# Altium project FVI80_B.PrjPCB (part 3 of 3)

## Sheet FVI80_HV_Power_Connector.SchDoc
size 431 x 279 mm; Date: Not shown in title block; ApprovedBy: Not shown in title block; CheckedBy: Not shown in title block; Author: Not shown in title block; CompanyName: Not shown in title block; Engineer: Not shown in title block; Organization: Not shown in title block; Address1: Not shown in title block; Address2: Not shown in title block; Address3: Not shown in title block; Address4: Not shown in title block; DocumentNumber: 10; Revision: Use project parameter SCH_Rev; SheetNumber: 10; SheetTotal: 11; PageSetup: Record=PageOptions¦CenterHorizontal=True¦CenterVertical=True¦PrintScale=1.00¦XCorrection=1.00¦YCorrection=1.00¦PrintKind=0¦BorderSize=5000000¦LeftOffset=0¦BottomOffset=0¦Orientation=2¦PaperLength=1000¦PaperWidth=1000¦Scale=100¦PaperSource=15¦PrintQuality=600¦MediaType=1¦DitherType=10¦PaperKind=Letter¦PrintScaleMode=1
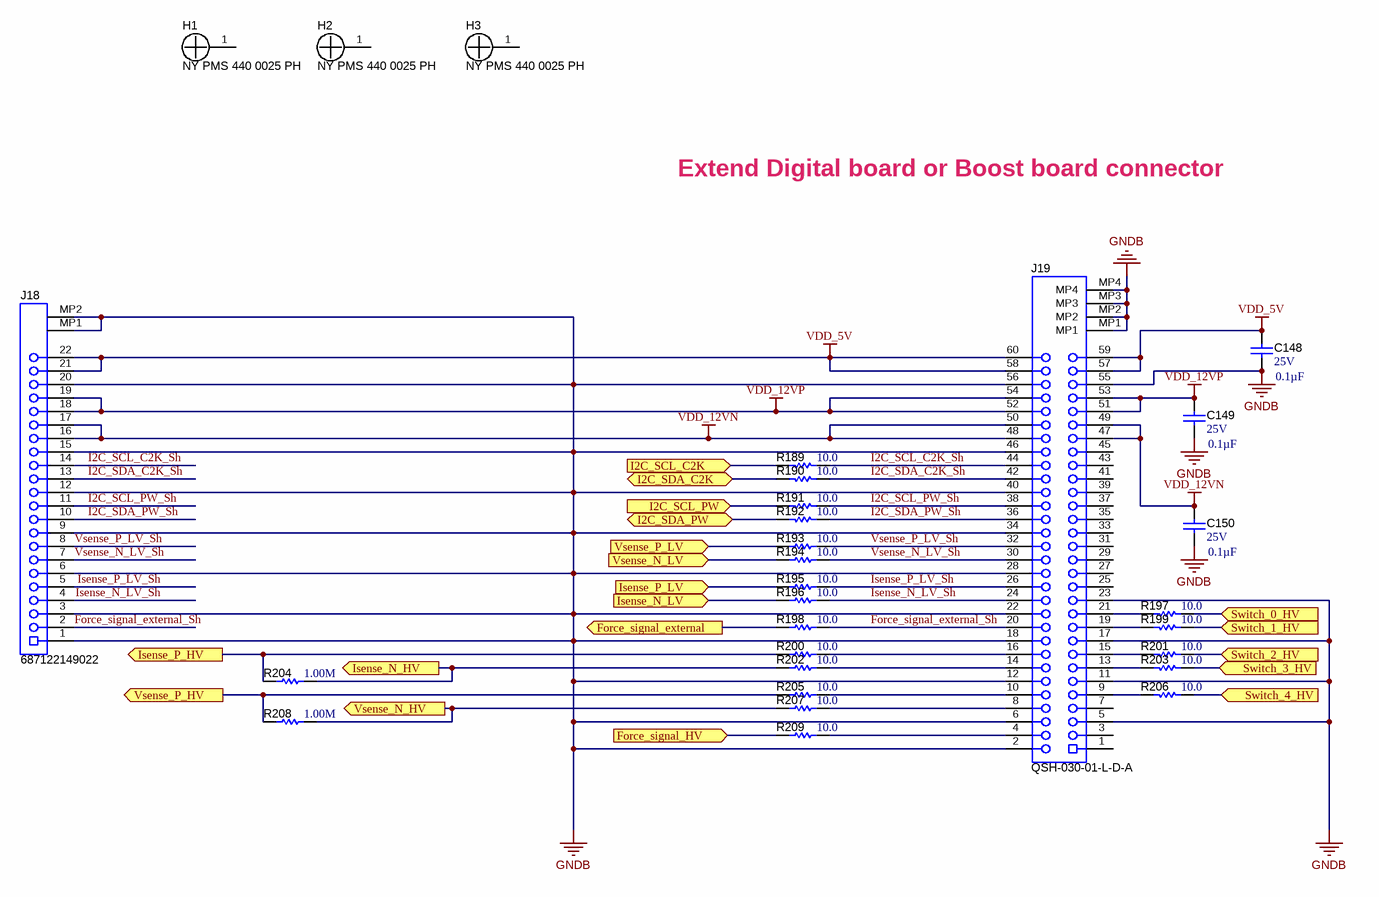
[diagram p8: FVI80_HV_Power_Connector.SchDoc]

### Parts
C148  VDC_V: 25V  ValueDisplayed: 0.1µF  [0402]  (hidden comment: CGA2B3X7R1E104K050BB)
C149  VDC_V: 25V  ValueDisplayed: 0.1µF  [0402]  (hidden comment: CGA2B3X7R1E104K050BB)
C150  VDC_V: 25V  ValueDisplayed: 0.1µF  [0402]  (hidden comment: CGA2B3X7R1E104K050BB)
H1  NY PMS 440 0025 PH  [NY PMS 440 0025 PH]
H2  NY PMS 440 0025 PH  [NY PMS 440 0025 PH]
H3  NY PMS 440 0025 PH  [NY PMS 440 0025 PH]
J18  687122149022  [Wurth_687122149022]
J19  QSH-030-01-L-D-A  [Samtec_QSH-030-01-X-D-A]
R189  ValueDisplayed: 10.0  [0402]  (hidden comment: MCR01MZPF10R0)
R190  ValueDisplayed: 10.0  [0402]  (hidden comment: MCR01MZPF10R0)
R191  ValueDisplayed: 10.0  [0402]  (hidden comment: MCR01MZPF10R0)
R192  ValueDisplayed: 10.0  [0402]  (hidden comment: MCR01MZPF10R0)
R193  ValueDisplayed: 10.0  [0402]  (hidden comment: CRCW040210R0FKED)
R194  ValueDisplayed: 10.0  [0402]  (hidden comment: CRCW040210R0FKED)
R195  ValueDisplayed: 10.0  [0402]  (hidden comment: CRCW040210R0FKED)
R196  ValueDisplayed: 10.0  [0402]  (hidden comment: CRCW040210R0FKED)
R197  ValueDisplayed: 10.0  [0402]  (hidden comment: MCR01MZPF10R0)
R198  ValueDisplayed: 10.0  [0402]  (hidden comment: CRCW040210R0FKED)
R199  ValueDisplayed: 10.0  [0402]  (hidden comment: MCR01MZPF10R0)
R200  ValueDisplayed: 10.0  [0402]  (hidden comment: CRCW040210R0FKED)
R201  ValueDisplayed: 10.0  [0402]  (hidden comment: MCR01MZPF10R0)
R202  ValueDisplayed: 10.0  [0402]  (hidden comment: CRCW040210R0FKED)
R203  ValueDisplayed: 10.0  [0402]  (hidden comment: MCR01MZPF10R0)
R204  ValueDisplayed: 1.00M  [0402]  (hidden comment: RC0402FR-071ML)
R205  ValueDisplayed: 10.0  [0402]  (hidden comment: CRCW040210R0FKED)
R206  ValueDisplayed: 10.0  [0402]  (hidden comment: MCR01MZPF10R0)
R207  ValueDisplayed: 10.0  [0402]  (hidden comment: CRCW040210R0FKED)
R208  ValueDisplayed: 1.00M  [0402]  (hidden comment: RC0402FR-071ML)
R209  ValueDisplayed: 10.0  [0402]  (hidden comment: CRCW040210R0FKED)

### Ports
Force_signal_external (out), Force_signal_HV (in), I2C_SCL_C2K (in), I2C_SCL_PW (in), I2C_SDA_C2K (bidir), I2C_SDA_PW (bidir), Isense_N_HV (out), Isense_N_LV (in), Isense_P_HV (out), Isense_P_LV (in), Switch_0_HV (in), Switch_1_HV (in), Switch_2_HV (in), Switch_3_HV (in), Switch_4_HV (in), Vsense_N_HV (out), Vsense_N_LV (in), Vsense_P_HV (out), Vsense_P_LV (in)

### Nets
GNDB: C148.2 C149.2 C150.2 J18.1 J18.3 J18.6 J18.9 J18.12 J18.15 J18.20 J18.MP1 J18.MP2 J19.2 J19.5 J19.6 J19.11 J19.12 J19.17 J19.18 J19.22 J19.23 J19.28 J19.34 J19.40 J19.46 J19.55 J19.56 J19.MP1 J19.MP2 J19.MP3 J19.MP4
VDD_5V: C148.1 J18.21 J18.22 J19.57 J19.58 J19.59 J19.60
VDD_12VN: C150.1 J18.16 J18.17 J19.47 J19.48 J19.49 J19.50
VDD_12VP: C149.1 J18.18 J18.19 J19.51 J19.52 J19.53 J19.54
Force_signal_external_Sh: J18.2 J19.20 R198.2
I2C_SCL_C2K_Sh: J18.14 J19.44 R189.2
I2C_SCL_IN: R189.1 ; port I2C_SCL_C2K
I2C_SCL_PW_Sh: J18.11 J19.38 R191.2
I2C_SDA_C2K_Sh: J18.13 J19.42 R190.2
I2C_SDA_IN: R190.1 ; port I2C_SDA_C2K
I2C_SDA_PW_Sh: J18.10 J19.36 R192.2
Isense_N_LV_Sh: J18.4 J19.24 R196.2
Isense_P_LV_Sh: J18.5 J19.26 R195.2
Vsense_N_LV_Sh: J18.7 J19.30 R194.2
Vsense_P_LV_Sh: J18.8 J19.32 R193.2
NetD1_2: R196.1 ; port Isense_N_LV
NetD2_2: R195.1 ; port Isense_P_LV
NetD3_2: R193.1 ; port Vsense_P_LV
NetD4_1: R194.1 ; port Vsense_N_LV
NetJ19_4: J19.4 R209.2
NetJ19_8: J19.8 R207.2
NetJ19_9: J19.9 R206.1
NetJ19_10: J19.10 R205.2
NetJ19_13: J19.13 R203.1
NetJ19_14: J19.14 R202.2
NetJ19_15: J19.15 R201.1
NetJ19_16: J19.16 R200.2
NetJ19_19: J19.19 R199.1
NetJ19_21: J19.21 R197.1
NetR114_1: R198.1 ; port Force_signal_external
NetR169_1: R192.1 ; port I2C_SDA_PW
NetR171_1: R191.1 ; port I2C_SCL_PW
NetR197_2: R197.2 ; port Switch_0_HV
NetR199_2: R199.2 ; port Switch_1_HV
NetR200_1: R200.1 R204.1 ; port Isense_P_HV
NetR201_2: R201.2 ; port Switch_2_HV
NetR202_1: R202.1 R204.2 ; port Isense_N_HV
NetR203_2: R203.2 ; port Switch_3_HV
NetR205_1: R205.1 R208.1 ; port Vsense_P_HV
NetR206_2: R206.2 ; port Switch_4_HV
NetR207_1: R207.1 R208.2 ; port Vsense_N_HV
NetR209_1: R209.1 ; port Force_signal_HV

Not connected (* = marked no-connect by the designer): H1 1; H2 1; H3 1; J19 1 3 7 25 27 29 31 33 35 37 39 41 43 45

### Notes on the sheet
- Extend Digital board or Boost board connector

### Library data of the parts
C148-C150 = CMP-0080610-1: CAP, CERM, 0.1 µF, 25 V,+/- 10%, X7R, AEC-Q200 Grade 1, 0402; Manufacturer: TDK; TaMin_C: -55°C; Polarized: N; SizeAreaWB_mm2: 3; U/M: EA; Value: 0.1uF; TaMax_C: 125°C; SizeZ_mm: 0.6; SizeX_mm: 1; SizeY_mm: 0.5; AEC Qualified: Y; Cap_F: 100nF; AEC Category: Q200
H1-H3 = CMP-0003617-1: Machine Screw, Round, #4-40 x 1/4, Nylon, Philips panhead; Manufacturer: B&F Fastener Supply; CompType: Hardware
J18 = CMP-0081902-1: FPC Connector, 0.5mm, 22 Pos, R/A, Tin, SMT; Manufacturer: Wurth Elektronik; Pitch_mm: 0.5; Gender: Female; Cert_UL: Y; Voltage_V: 50V; Current_A: 500mA; Row_Count: 1; CompType: FFC or FPC
J19 = CMP-0075524-1: Receptacle, 0.5 mm, 30x2, Gold, TH; Manufacturer: Samtec; Pitch_mm: 0.5; Gender: Female; Green_REACh: Passed; CT: False; Shrouded: N; RowSpacing_mm: 5.73; Green_Lifecycle: Active; Row_Count: 2
R189-R192 R197 R199 R201 R203 R206 = CMP-0025963-3: RES, 10.0, 1%, 0.063 W, AEC-Q200 Grade 0, 0402; Manufacturer: Vishay-Dale; PartNumber: CRCW040210R0FKED; Power_W: 63mW; TempCo: 100 ppm/C; Value_Code: 10R0; Value: 10.0; EIA_Code: E96; Res_ohm: 10; SizeX_mm: 1; SizeY_mm: 0.5; SizeZ_mm: 0.6; Value2: 0.063W; AEC Qualified: Y; VDC_V: 50V; AEC Category: Q200; AEC Grade: 0
R193-R196 R198 R200 R202 R205 R207 R209 = CMP-0025963-3: RES, 10.0, 1%, 0.063 W, AEC-Q200 Grade 0, 0402; Manufacturer: Vishay-Dale; Power_W: 63mW; TempCo: 100 ppm/C; Value_Code: 10R0; Value: 10.0; EIA_Code: E96; Res_ohm: 10; SizeX_mm: 1; SizeY_mm: 0.5; SizeZ_mm: 0.6; Value2: 0.063W; AEC Qualified: Y; VDC_V: 50V; AEC Category: Q200; AEC Grade: 0
R204 R208 = CMP-0026727-1: RES, 1.00 M, 1%, 0.063 W, 0402; Manufacturer: Yageo America; Power_W: 63mW; TempCo: 100 ppm/C; Value_Code: 1M00; U/M: EA; Value: 1.00Meg; EIA_Code: E96; Res_ohm: 1M; SizeX_mm: 1; SizeY_mm: 0.5; SizeZ_mm: 0.6; Value2: 0.063W; AEC Category: Q200

## Sheet FVI80_Signal_ADC93.SchDoc
size 431 x 279 mm; Date: Not shown in title block; ApprovedBy: Not shown in title block; CheckedBy: Not shown in title block; Author: Not shown in title block; CompanyName: Not shown in title block; Engineer: Not shown in title block; Organization: Not shown in title block; Address1: Not shown in title block; Address2: Not shown in title block; Address3: Not shown in title block; Address4: Not shown in title block; DocumentNumber: 7; Revision: Use project parameter SCH_Rev; SheetNumber: 7; SheetTotal: 11; PageSetup: Record=PageOptions¦CenterHorizontal=True¦CenterVertical=True¦PrintScale=1.00¦XCorrection=1.00¦YCorrection=1.00¦PrintKind=0¦BorderSize=5000000¦LeftOffset=0¦BottomOffset=0¦Orientation=2¦PaperLength=1000¦PaperWidth=1000¦Scale=100¦PaperSource=15¦PrintQuality=600¦MediaType=1¦DitherType=10¦PaperKind=Letter¦PrintScaleMode=1
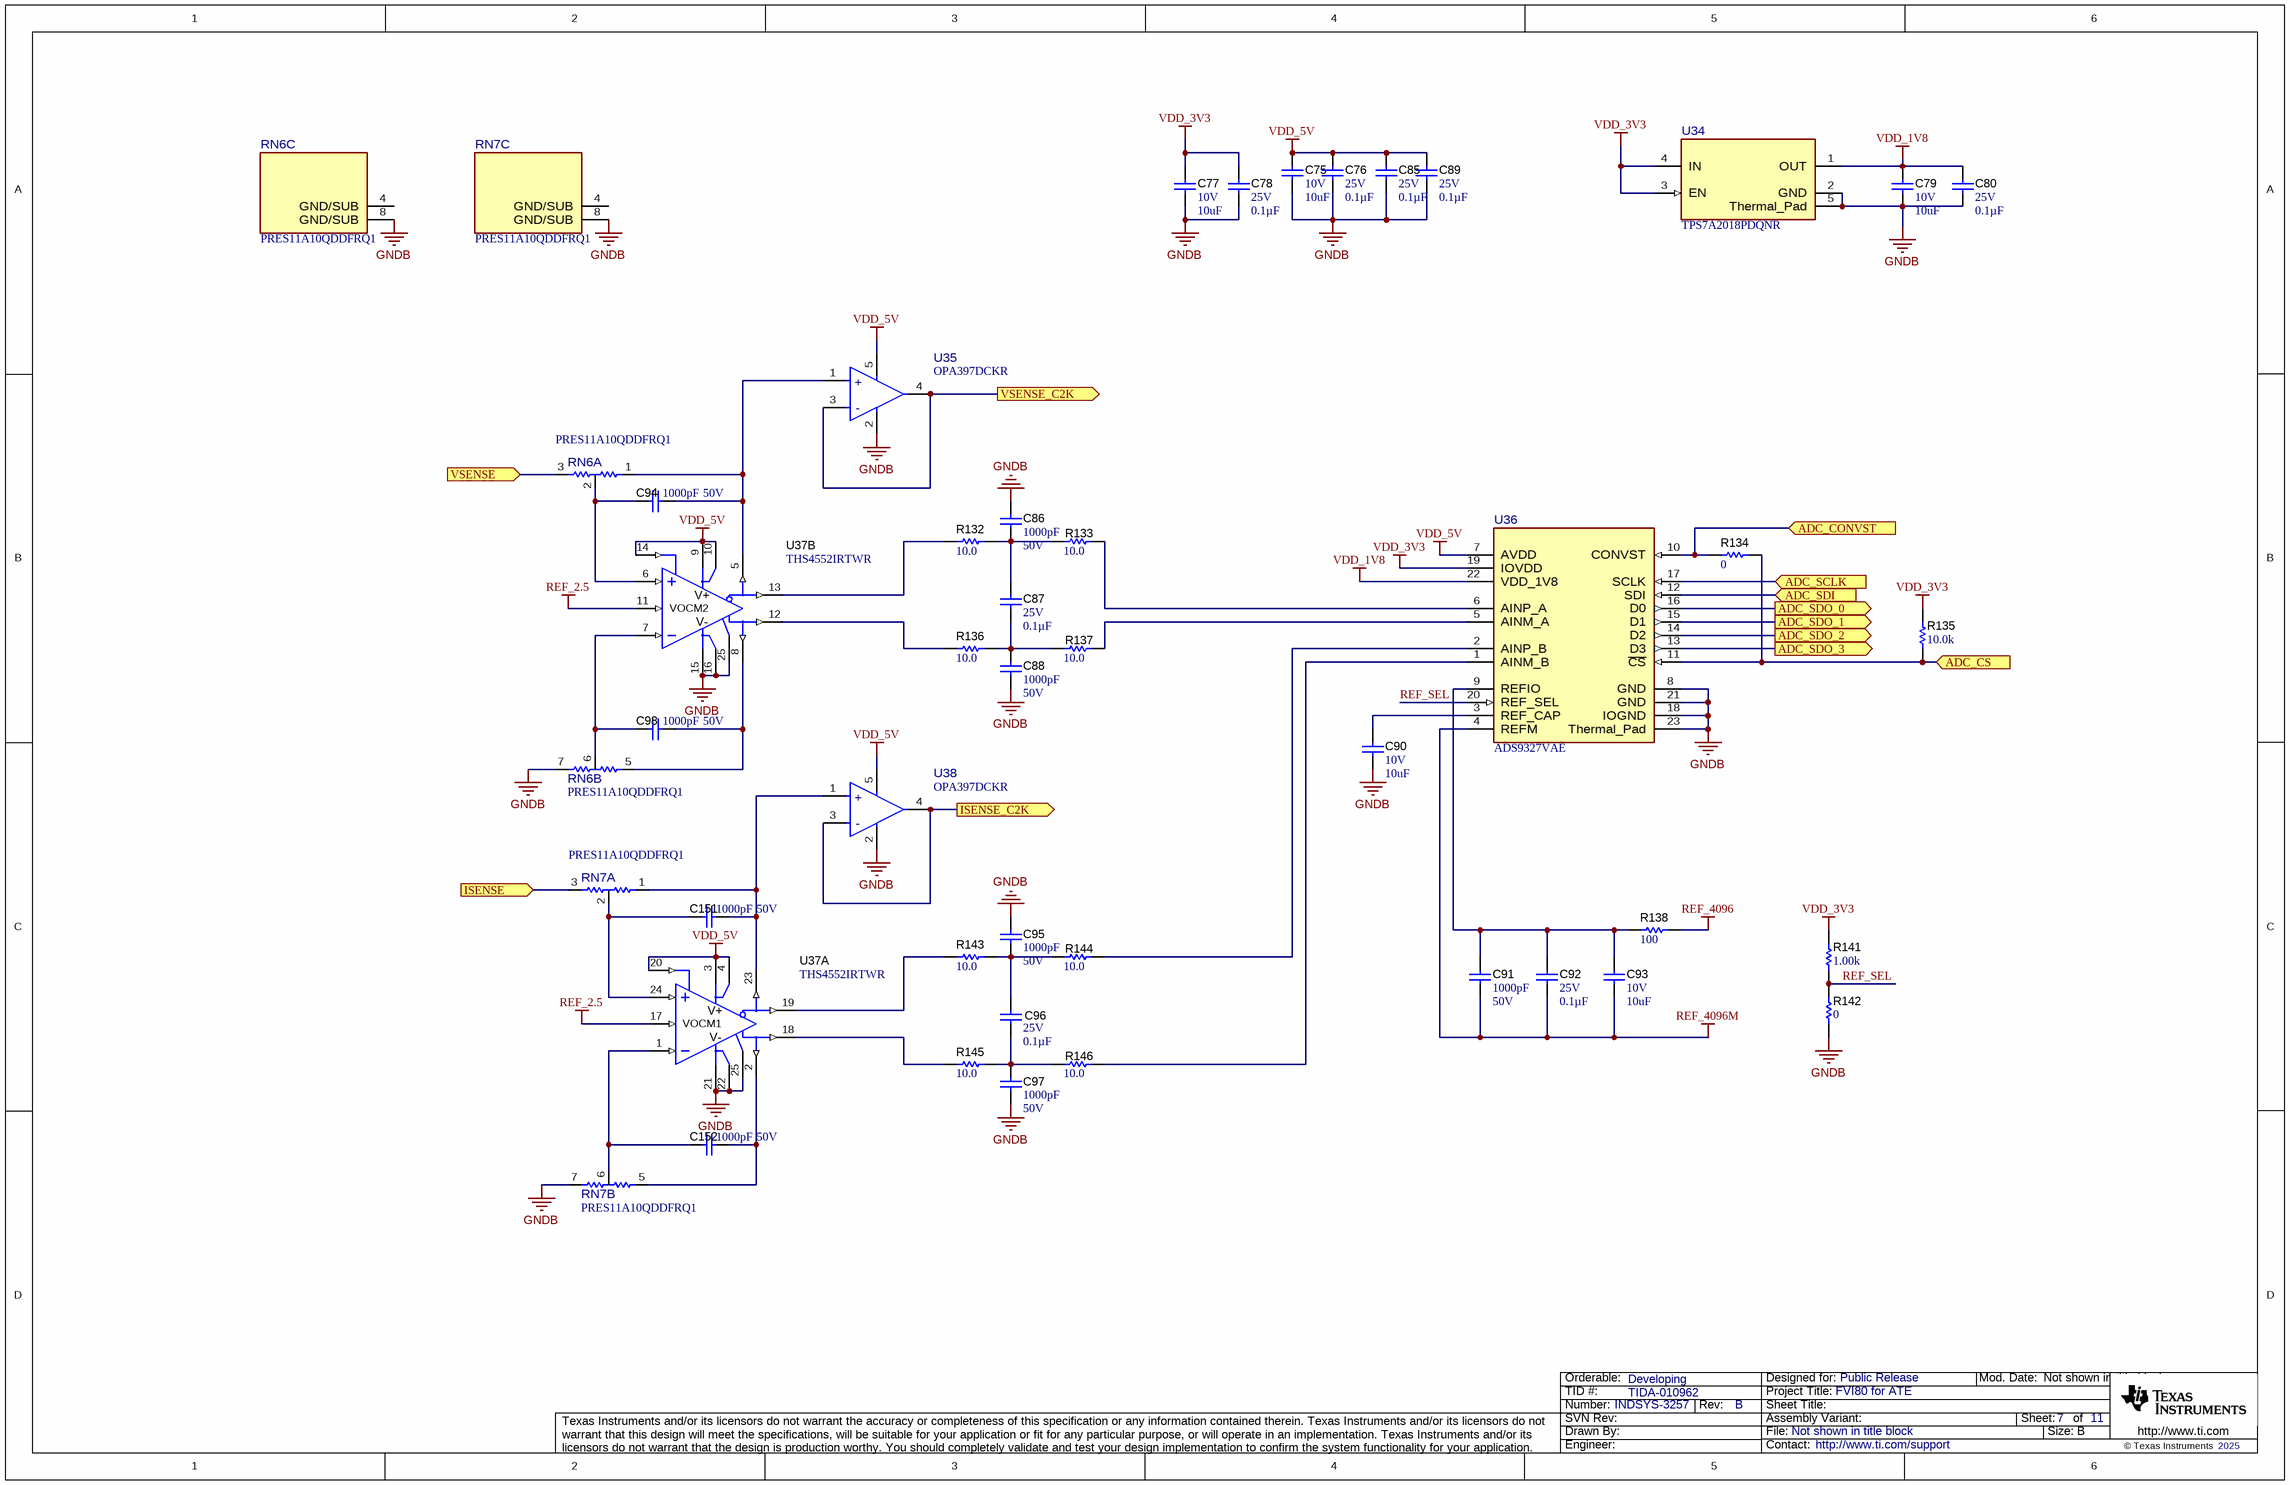
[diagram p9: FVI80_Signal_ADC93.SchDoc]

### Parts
C75  VDC_V: 10V  ValueDisplayed: 10uF  [0402]  (hidden comment: GRM155R61A106ME11D)
C76  VDC_V: 25V  ValueDisplayed: 0.1µF  [0402]  (hidden comment: CGA2B3X7R1E104K050BB)
C77  VDC_V: 10V  ValueDisplayed: 10uF  [0402]  (hidden comment: GRM155R61A106ME11D)
C78  VDC_V: 25V  ValueDisplayed: 0.1µF  [0402]  (hidden comment: CGA2B3X7R1E104K050BB)
C79  VDC_V: 10V  ValueDisplayed: 10uF  [0402]  (hidden comment: GRM155R61A106ME11D)
C80  VDC_V: 25V  ValueDisplayed: 0.1µF  [0402]  (hidden comment: CGA2B3X7R1E104K050BB)
C85  VDC_V: 25V  ValueDisplayed: 0.1µF  [0402]  (hidden comment: CGA2B3X7R1E104K050BB)
C86  ValueDisplayed: 1000pF  VDC_V: 50V  [0402]  (hidden comment: CGA2B2X8R1H102K050BA)
C87  VDC_V: 25V  ValueDisplayed: 0.1µF  [0402]  (hidden comment: CGA2B3X7R1E104K050BB)
C88  ValueDisplayed: 1000pF  VDC_V: 50V  [0402]  (hidden comment: CGA2B2X8R1H102K050BA)
C89  VDC_V: 25V  ValueDisplayed: 0.1µF  [0402]  (hidden comment: CGA2B3X7R1E104K050BB)
C90  VDC_V: 10V  ValueDisplayed: 10uF  [0402]  (hidden comment: GRM155R61A106ME11D)
C91  ValueDisplayed: 1000pF  VDC_V: 50V  [0402]  (hidden comment: CGA2B2X8R1H102K050BA)
C92  VDC_V: 25V  ValueDisplayed: 0.1µF  [0402]  (hidden comment: CGA2B3X7R1E104K050BB)
C93  VDC_V: 10V  ValueDisplayed: 10uF  [0402]  (hidden comment: GRM155R61A106ME11D)
C94  ValueDisplayed: 1000pF  VDC_V: 50V  [0402]  (hidden comment: CGA2B2X8R1H102K050BA)
C95  ValueDisplayed: 1000pF  VDC_V: 50V  [0402]  (hidden comment: CGA2B2X8R1H102K050BA)
C96  VDC_V: 25V  ValueDisplayed: 0.1µF  [0402]  (hidden comment: CGA2B3X7R1E104K050BB)
C97  ValueDisplayed: 1000pF  VDC_V: 50V  [0402]  (hidden comment: CGA2B2X8R1H102K050BA)
C98  ValueDisplayed: 1000pF  VDC_V: 50V  [0402]  (hidden comment: CGA2B2X8R1H102K050BA)
C151  ValueDisplayed: 1000pF  VDC_V: 50V  [0402]  (hidden comment: CGA2B2X8R1H102K050BA)
C152  ValueDisplayed: 1000pF  VDC_V: 50V  [0402]  (hidden comment: CGA2B2X8R1H102K050BA)
R132  ValueDisplayed: 10.0  [0402]  (hidden comment: CRCW040210R0FKED)
R133  ValueDisplayed: 10.0  [0402]  (hidden comment: MCR01MZPF10R0)
R134  ValueDisplayed: 0  [0402]  (hidden comment: CRCW04020000Z0ED)
R135  ValueDisplayed: 10.0k  [0402]  (hidden comment: RK73H1ETTP1002F)
R136  ValueDisplayed: 10.0  [0402]  (hidden comment: CRCW040210R0FKED)
R137  ValueDisplayed: 10.0  [0402]  (hidden comment: MCR01MZPF10R0)
R138  ValueDisplayed: 100  [0402]  (hidden comment: RMCF0402JT100R)
R141  ValueDisplayed: 1.00k  [0402]  (hidden comment: CRCW04021K00FKED)
R142  ValueDisplayed: 0  [0402]  (hidden comment: CRCW04020000Z0ED)
R143  ValueDisplayed: 10.0  [0402]  (hidden comment: CRCW040210R0FKED)
R144  ValueDisplayed: 10.0  [0402]  (hidden comment: MCR01MZPF10R0)
R145  ValueDisplayed: 10.0  [0402]  (hidden comment: CRCW040210R0FKED)
R146  ValueDisplayed: 10.0  [0402]  (hidden comment: MCR01MZPF10R0)
RN6  PRES11A10QDDFRQ1  [DDF0008A-MFG]  (parts A,B,C of 3)
RN7  PRES11A10QDDFRQ1  [DDF0008A-MFG]  (parts A,B,C of 3)
U34  TPS7A2018PDQNR  [DQN0004A-MFG]
U35  OPA397DCKR  [DCK0005A-MFG]
U36  ADS9327VAE  [VAE0022A-MFG]
U37  THS4552IRTWR  [RTW0024A]  (parts A,B of 2)
U38  OPA397DCKR  [DCK0005A-MFG]

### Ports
ADC_CONVST (in), ADC_CS (in), ADC_SCLK (in), ADC_SDI (in), ADC_SDO_0 (out), ADC_SDO_1 (out), ADC_SDO_2 (out), ADC_SDO_3 (out), ISENSE (in), ISENSE_C2K (out), VSENSE (in), VSENSE_C2K (out)

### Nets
GNDB: C75.2 C76.1 C77.2 C78.1 C79.2 C80.1 C85.1 C86.2 C88.1 C89.1 C90.2 C91.2 C92.1 C93.2 C95.2 C97.1 R142.1 RN6.7(RIN2) RN6.8(GND/SUB) RN7.7(RIN2) RN7.8(GND/SUB) U34.2(GND) U34.5(Thermal_Pad) U35.2(V-) U36.4(REFM) U36.8(GND) U36.18(IOGND) U36.21(GND) U36.23(Thermal_Pad) U37.15(-VS2) U37.16(-VS2) U37.21(-VS1) U37.22(-VS1) U37.25(EP) U38.2(V-)  [also labelled REF_4096M]
REF_2.5: U37.11(VOCM2) U37.17(VOCM1)
REF_4096: R138.2
VDD_1V8: C79.1 C80.2 U34.1(OUT) U36.22(VDD_1V8)
VDD_3V3: C77.1 C78.2 R135.2 R141.2 U34.3(EN) U34.4(IN) U36.19(IOVDD)
VDD_5V: C75.1 C76.2 C85.2 C89.2 U35.5(V+) U36.7(AVDD) U37.3(+VS1) U37.4(+VS1) U37.9(+VS2) U37.10(+VS2) U37.14(~{DISABLE2}) U37.20(~{DISABLE1}) U38.5(V+)
REF_SEL: R141.1 R142.2 U36.20(REF_SEL)
NetC19_1: RN7.3(RG1) ; port ISENSE
NetC36_1: RN6.3(RG1) ; port VSENSE
NetC86_1: C86.1 C87.2 R132.2 R133.1
NetC87_1: C87.1 C88.2 R136.2 R137.1
NetC90_1: C90.1 U36.3(REF_CAP)
NetC91_1: C91.1 C92.2 C93.1 R138.1 U36.9(REFIO)
NetC94_1: C94.1 RN6.1(RIN1) U35.1(+IN) U37.5(-FB2)
NetC94_2: C94.2 RN6.2(RMID1) U37.6(+IN2)
NetC95_1: C95.1 C96.2 R143.2 R144.1
NetC96_1: C96.1 C97.2 R145.2 R146.1
NetC98_1: C98.1 RN6.5(RG2) U37.8(+FB2)
NetC98_2: C98.2 RN6.6(RMID2) U37.7(-IN2)
NetC151_1: C151.1 RN7.1(RIN1) U37.23(-FB1) U38.1(+IN)
NetC151_2: C151.2 RN7.2(RMID1) U37.24(+IN1)
NetC152_1: C152.1 RN7.5(RG2) U37.2(+FB1)
NetC152_2: C152.2 RN7.6(RMID2) U37.1(-IN1)
NetR132_1: R132.1 U37.13(-OUT2)
NetR133_2: R133.2 U36.6(AINP_A)
NetR134_1: R134.1 U36.10(CONVST) ; port ADC_CONVST
NetR134_2: R134.2 R135.1 U36.11(~{CS}) ; port ADC_CS
NetR136_1: R136.1 U37.12(+OUT2)
NetR137_2: R137.2 U36.5(AINM_A)
NetR143_1: R143.1 U37.19(-OUT1)
NetR144_2: R144.2 U36.2(AINP_B)
NetR145_1: R145.1 U37.18(+OUT1)
NetR146_2: R146.2 U36.1(AINM_B)
NetR163_2: U38.3(-IN) U38.4(OUT) ; port ISENSE_C2K
NetR167_2: U35.3(-IN) U35.4(OUT) ; port VSENSE_C2K
NetR170_2: U36.16(D0) ; port ADC_SDO_0
NetR172_2: U36.15(D1) ; port ADC_SDO_1
NetR174_2: U36.14(D2) ; port ADC_SDO_2
NetR178_1: U36.12(SDI) ; port ADC_SDI
NetR179_1: U36.13(D3) ; port ADC_SDO_3
NetR181_1: U36.17(SCLK) ; port ADC_SCLK

Not connected (* = marked no-connect by the designer): RN6 4(GND/SUB); RN7 4(GND/SUB)

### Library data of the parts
C75 C77 C79 C90 C93 = CMP-0006564-3: CAP, CERM, 10 uF, 10 V, +/- 20%, X5R, 0402; Manufacturer: MuRata; TaMin_C: -55°C; Polarized: N; SizeAreaWB_mm2: 3; Value1: Unknown; U/M: EA; Value: 10uF; TaMax_C: 85°C; SizeZ_mm: 0.6; SizeX_mm: 1; SizeY_mm: 0.5; Cap_F: 10µF; AEC Category: Q200
C76 C78 C80 C85 C87 C89 C92 C96 = CMP-0080610-1: as C148-C150 on sheet FVI80_HV_Power_Connector
C86 C88 C91 C94 C95 C97 C98 C151 C152 = CMP-0860997-1: CAP, CERM, 1000 pF, 50 V,+/- 10%, X8R, AEC-Q200 Grade 0, 0402; Manufacturer: TDK; SizeArea_mm2: 0.5; U/M: EA; SizeX_mm: 1; Polarized: N; AEC Grade: 0; AEC Qualified: Y; TaMin_C: -55°C; Value: 1000pF; TaMax_C: 150°C; SizeZ_mm: 0.6; Cap_F: 1nF; SizeAreaWB_mm2: 3; AEC Category: Q200
R132 R136 R143 R145 = CMP-0025963-3: RES, 10.0, 1%, 0.063 W, AEC-Q200 Grade 0, 0402; Manufacturer: Vishay-Dale; Power_W: 63mW; TempCo: 100 ppm/C; Value_Code: 10R0; Value: 10.0; Res_ohm: 10; SizeX_mm: 1; SizeY_mm: 0.5; SizeZ_mm: 0.6; Value2: 0.063W; AEC Qualified: Y; VDC_V: 50V; AEC Grade: 0; AEC Category: Q200; EIA_Code: E96
R133 R137 R144 R146 = CMP-0025963-3: RES, 10.0, 1%, 0.063 W, AEC-Q200 Grade 0, 0402; Manufacturer: Vishay-Dale; PartNumber: CRCW040210R0FKED; Power_W: 63mW; TempCo: 100 ppm/C; Value_Code: 10R0; Value: 10.0; EIA_Code: E96; Res_ohm: 10; SizeX_mm: 1; SizeY_mm: 0.5; SizeZ_mm: 0.6; Value2: 0.063W; AEC Qualified: Y; VDC_V: 50V; AEC Grade: 0; AEC Category: Q200
R134 R142 = CMP-0026822-3: RES, 0, 5%, 0.063 W, AEC-Q200 Grade 0, 0402; Manufacturer: Vishay-Dale; Value: 0; Value_Code: 0000; Power_W: 63mW; Value2: 0.063W; VDC_V: 50V; TempCo: 200 ppm/C; SizeArea_mm2: 0.5; SizeX_mm: 1; SizeZ_mm: 0.6; EIA_Code: E24; AEC Category: Q200; AEC Qualified: Y
R135 = CMP-0026748-1: RES, 10.0 k, 1%, 0.063 W, AEC-Q200 Grade 0, 0402; Manufacturer: KOA Speer; Power_W: 63mW; TempCo: 100 ppm/C; Value_Code: 10k0; U/M: EA; Value: 10.0k; EIA_Code: E96; Res_ohm: 10k; SizeX_mm: 1; SizeY_mm: 0.5; SizeZ_mm: 0.6; Value2: 0.063W; AEC Qualified: Y; VDC_V: 50V; AEC Grade: 0; AEC Category: Q200
R138 = CMP-0026763-1: RES, 100, 1%, 0.063 W, AEC-Q200 Grade 0, 0402; Manufacturer: Stackpole Electronics Inc; Power_W: 63mW; TempCo: 100 ppm/C; Value_Code: 100R; U/M: EA; Value: 100; EIA_Code: E96; SizeX_mm: 1; SizeY_mm: 0.5; SizeZ_mm: 0.6; Value2: 0.063W; AEC Qualified: Y; AEC Grade: 0; AEC Category: Q200
R141 = CMP-0026071-3: RES, 1.00 k, 1%, 0.063 W, AEC-Q200 Grade 0, 0402; Manufacturer: Vishay-Dale; Power_W: 63mW; TempCo: 100 ppm/C; Value_Code: 1k00; Value: 1.00k; EIA_Code: E96; Res_ohm: 1k; SizeX_mm: 1; SizeY_mm: 0.5; SizeZ_mm: 0.6; Value2: 0.063W; AEC Qualified: Y; VDC_V: 50V; AEC Category: Q200; AEC Grade: 0
RN6 RN7 = CMP-0123029-1: Automotive low-noise matched thin-film resistor divider network with 1kΩ fixed input 8-SOT-23-THIN -40 to 125; Manufacturer: Texas Instruments; SizeZ_mm: 1.1mm; AEC Qualified: Yes; AEC Grade: Grade 1; Number Of Resistors: 4; Standoff Height: 0mm; TaMax_C: +125°C; TaMin_C: -40°C; TempCo: 18ppm/°C; TJmax_C: +150°C; Tolerance_%: 2%
U34 = CMP-0123489-1: Linear Voltage Regulator IC Positive Fixed 1 Output 300mA 4-X2SON (1x1); Manufacturer: Texas Instruments; SizeZ_mm: 0.4mm; AEC Qualified: No; Accuracy Percentage: 1.5%; Dropout Voltage: 200mV; Max Supply Voltage: 6V; Min Supply Voltage: 2.1V; Nominal Supply Current: 6.5uA; Number Of Outputs: 1; Output Voltage: 1.8V; Standoff Height: 0mm; TJmax_C: +125°C
U35 U38 = CMP-0126581-1: Standard (General Purpose) Amplifier 1 Circuit Push-Pull, Rail-to-Rail SC-70-5; Manufacturer: Texas Instruments; SizeZ_mm: 1.1mm; AEC Qualified: No; Gain Bandwidth: 13MHz; Input Bias Current: 0.01pA; Input Offset Voltage: 10uV; Max Dual Supply Voltage: 2.75V; Max Supply Voltage: 5.5V; Min Dual Supply Voltage: 850mV; Min Supply Voltage: 1.7V; Nominal Supply Current: 1.22mA; Number Of Channels: 1; Output Current Per Channel: 65mA; Response Time: 1us; Standoff Height: 0mm; TaMax_C: +125°C; TaMin_C: -40°C; TJmax_C: +150°C; Voltage Gain: 132dB
U36 = CMP-0121626-2: Dual, Simultaneous-Sampling, 16-Bit, 5 MSPS SAR ADC, VQFN-HR22; Manufacturer: Texas Instruments; SizeZ_mm: 1mm; AEC Qualified: No; Data Polarity: Differential; Interface: SPI; Max Supply Voltage: 5.25V; Min Supply Voltage: 1.75V; Number Of Channels: 2; Resolution: 16bits; Sampling Rate: 5Msps; Standoff Height: 0mm; TaMax_C: +125°C; TaMin_C: -40°C; TJmax_C: +150°C; AEC Category: Q200; CompType: IC
U37 = CMP-0014032-1: Low-Noise, Precision, 150-MHz, Fully Differential Amplifier, RTW0024A (WQFN-24); Alternate PartNumber: THS4552IRTWT; Alternate Manufacturer: Texas Instruments; SizeAreaWB_mm2: 25; U/M: EA; SizeZ_mm: 0.8; SizeX_mm: 4; SizeArea_mm2: 16; CompType: IC

## Sheet FVI80_Power_Rsense_series.SchDoc
size 431 x 279 mm; Date: Not shown in title block; ApprovedBy: Not shown in title block; CheckedBy: Not shown in title block; Author: Not shown in title block; CompanyName: Not shown in title block; Engineer: Not shown in title block; Organization: Not shown in title block; Address1: Not shown in title block; Address2: Not shown in title block; Address3: Not shown in title block; Address4: Not shown in title block; DocumentNumber: 3; Revision: Use project parameter SCH_Rev; SheetNumber: 3; SheetTotal: 11; PageSetup: Record=PageOptions¦CenterHorizontal=True¦CenterVertical=True¦PrintScale=1.00¦XCorrection=1.00¦YCorrection=1.00¦PrintKind=0¦BorderSize=5000000¦LeftOffset=0¦BottomOffset=0¦Orientation=2¦PaperLength=1000¦PaperWidth=1000¦Scale=100¦PaperSource=15¦PrintQuality=600¦MediaType=1¦DitherType=10¦PaperKind=Letter¦PrintScaleMode=1
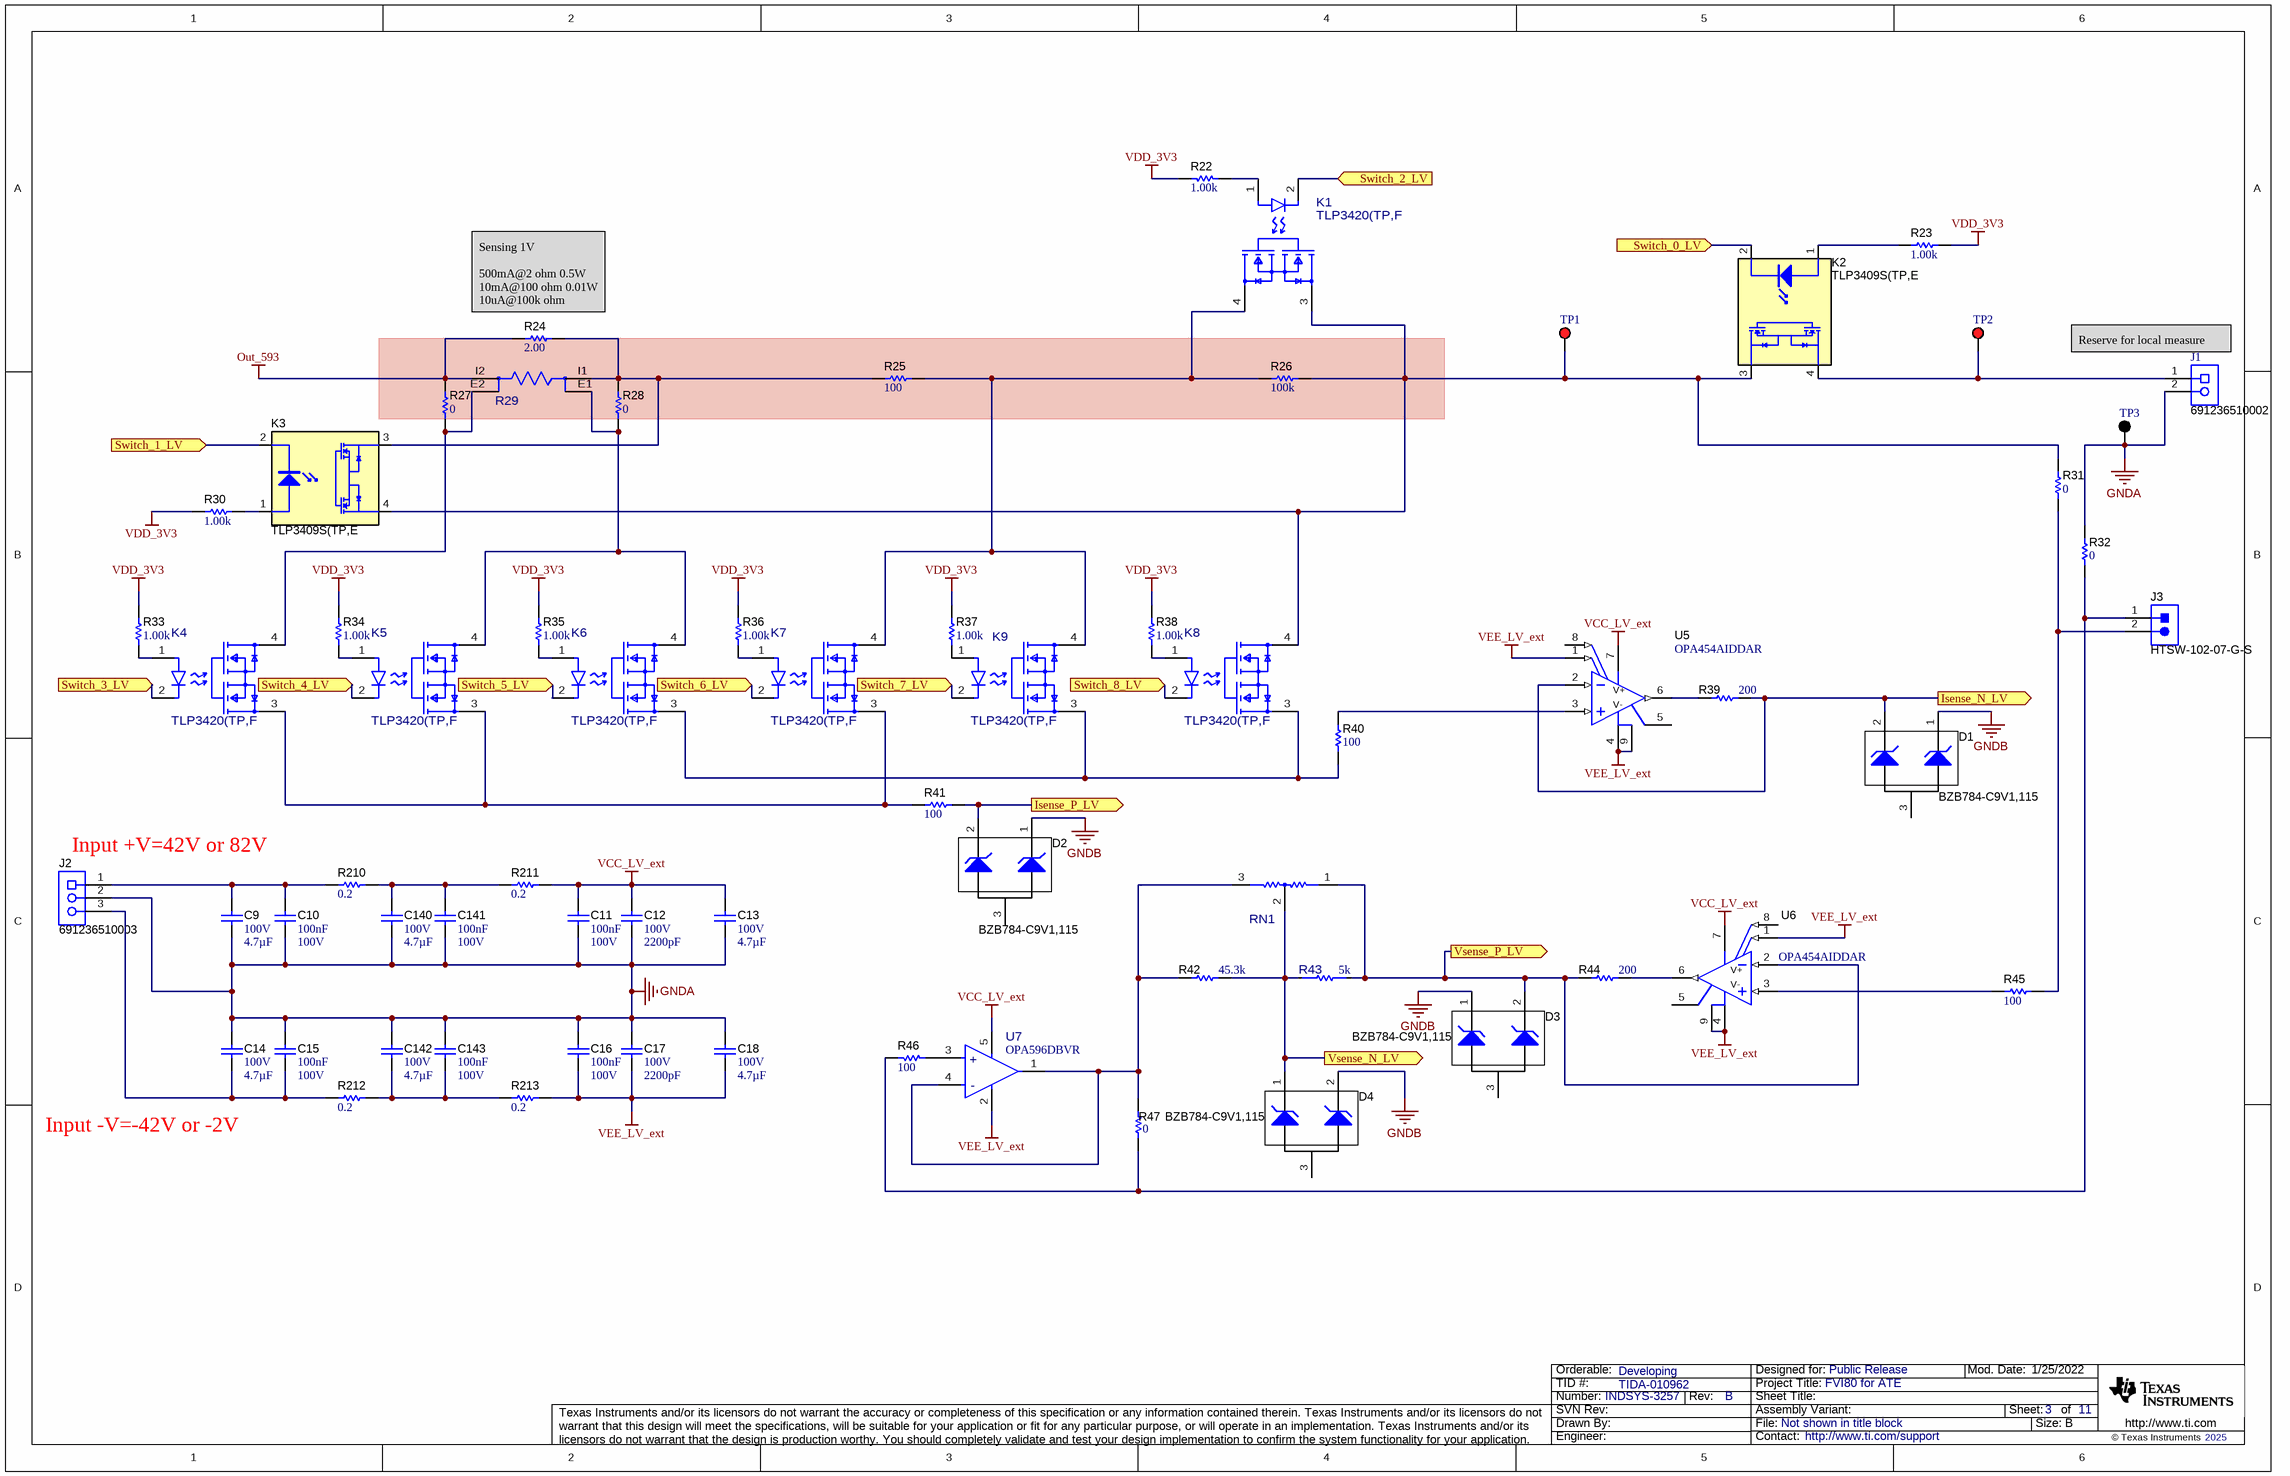
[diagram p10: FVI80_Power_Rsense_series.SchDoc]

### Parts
C9  VDC_V: 100V  ValueDisplayed: 4.7µF  [1206_190]  (hidden comment: 12061Z475MAT2A)
C10  Cap_F: 100nF  VDC_V: 100V  [0402]  (hidden comment: GRM155R62A104KE14D)
C11  Cap_F: 100nF  VDC_V: 100V  [0402]  (hidden comment: GRM155R62A104KE14D)
C12  VDC_V: 100V  ValueDisplayed: 2200pF  [0402]  (hidden comment: GRM155R72A222KA01D)
C13  VDC_V: 100V  ValueDisplayed: 4.7µF  [1206_190]  (hidden comment: 12061Z475MAT2A)
C14  VDC_V: 100V  ValueDisplayed: 4.7µF  [1206_190]  (hidden comment: 12061Z475MAT2A)
C15  Cap_F: 100nF  VDC_V: 100V  [0402]  (hidden comment: GRM155R62A104KE14D)
C16  Cap_F: 100nF  VDC_V: 100V  [0402]  (hidden comment: GRM155R62A104KE14D)
C17  VDC_V: 100V  ValueDisplayed: 2200pF  [0402]  (hidden comment: GRM155R72A222KA01D)
C18  VDC_V: 100V  ValueDisplayed: 4.7µF  [1206_190]  (hidden comment: 12061Z475MAT2A)
C140  VDC_V: 100V  ValueDisplayed: 4.7µF  [1206_190]  (hidden comment: 12061Z475MAT2A)
C141  Cap_F: 100nF  VDC_V: 100V  [0402]  (hidden comment: GRM155R62A104KE14D)
C142  VDC_V: 100V  ValueDisplayed: 4.7µF  [1206_190]  (hidden comment: 12061Z475MAT2A)
C143  Cap_F: 100nF  VDC_V: 100V  [0402]  (hidden comment: GRM155R62A104KE14D)
D1  BZB784-C9V1,115  [SOT-323]
D2  BZB784-C9V1,115  [SOT-323]
D3  BZB784-C9V1,115  [SOT-323]
D4  BZB784-C9V1,115  [SOT-323]
J1  691236510002  [Wurth_691236510002]
J2  691236510003  [Wurth_691236510003]
J3  HTSW-102-07-G-S  [Samtec_HTSW-102-07-G-S]
K1  TLP3420(TP,F  [FP-TLP3420(TP,F_SMD4-MFG]
K2  TLP3409S(TP,E  [Omron_S-VSON4]
K3  TLP3409S(TP,E  [Omron_S-VSON4]
K4  TLP3420(TP,F  [FP-TLP3420(TP,F_SMD4-MFG]
K5  TLP3420(TP,F  [FP-TLP3420(TP,F_SMD4-MFG]
K6  TLP3420(TP,F  [FP-TLP3420(TP,F_SMD4-MFG]
K7  TLP3420(TP,F  [FP-TLP3420(TP,F_SMD4-MFG]
K8  TLP3420(TP,F  [FP-TLP3420(TP,F_SMD4-MFG]
K9  TLP3420(TP,F  [FP-TLP3420(TP,F_SMD4-MFG]
R22  ValueDisplayed: 1.00k  [0402]  (hidden comment: CRCW04021K00FKED)
R23  ValueDisplayed: 1.00k  [0402]  (hidden comment: CRCW04021K00FKED)
R24  ValueDisplayed: 2.00  [1210]  (hidden comment: ERJ-14BQF2R0U)
R25  ValueDisplayed: 100  [0805_HV]  (hidden comment: CRCW0805100RFKEA)
R26  ValueDisplayed: 100k  [0805_HV]  (hidden comment: CRCW0805100KFKEA)
R27  ValueDisplayed: 0  [0402]  (hidden comment: CRCW04020000Z0ED)
R28  ValueDisplayed: 0  [0402]  (hidden comment: CRCW04020000Z0ED)
R29  Y08502R00000F9R  [FP-Y08502R00000F9R_2516-MFG]  (value not drawn)
R30  ValueDisplayed: 1.00k  [0402]  (hidden comment: CRCW04021K00FKED)
R31  ValueDisplayed: 0  [0402]  (hidden comment: CRCW04020000Z0ED)
R32  ValueDisplayed: 0  [0402]  (hidden comment: CRCW04020000Z0ED)
R33  ValueDisplayed: 1.00k  [0402]  (hidden comment: CRCW04021K00FKED)
R34  ValueDisplayed: 1.00k  [0402]  (hidden comment: CRCW04021K00FKED)
R35  ValueDisplayed: 1.00k  [0402]  (hidden comment: CRCW04021K00FKED)
R36  ValueDisplayed: 1.00k  [0402]  (hidden comment: CRCW04021K00FKED)
R37  ValueDisplayed: 1.00k  [0402]  (hidden comment: CRCW04021K00FKED)
R38  ValueDisplayed: 1.00k  [0402]  (hidden comment: CRCW04021K00FKED)
R39  ValueDisplayed: 200  [0805_HV]  (hidden comment: CRCW0805200RFKEA)
R40  ValueDisplayed: 100  [0402]  (hidden comment: RMCF0402JT100R)
R41  ValueDisplayed: 100  [0402]  (hidden comment: RMCF0402JT100R)
R42  ValueDisplayed: 45.3k  [0805_HV]  (hidden comment: ERJ-6ENF4532V)
R43  Res_ohm: 5k  [FP-CRCW08055K00FKTA_0805-MFG]  (hidden comment: CRCW08055K00FKTA)
R44  ValueDisplayed: 200  [0805_HV]  (hidden comment: CRCW0805200RFKEA)
R45  ValueDisplayed: 100  [0402]  (hidden comment: RMCF0402JT100R)
R46  ValueDisplayed: 100  [0402]  (hidden comment: RMCF0402JT100R)
R47  ValueDisplayed: 0  [0402]  (hidden comment: CRCW04020000Z0ED)
R210  ValueDisplayed: 0.2  [0603]  (hidden comment: RCWE0603R200FKEA)
R211  ValueDisplayed: 0.2  [0603]  (hidden comment: RCWE0603R200FKEA)
R212  ValueDisplayed: 0.2  [0603]  (hidden comment: RCWE0603R200FKEA)
R213  ValueDisplayed: 0.2  [0603]  (hidden comment: RCWE0603R200FKEA)
RN1  Y0115V0030VV9L  [FP-Y0115V0030VV9L_RADIAL-MFG]  (value not drawn)
TP1  5000  [Keystone5000]  (value not drawn)
TP2  5000  [Keystone5000]  (value not drawn)
TP3  5001  [Keystone5001]  (value not drawn)
U5  OPA454AIDDAR  [DDA0008J]
U6  OPA454AIDDAR  [DDA0008J]
U7  OPA596DBVR  [DBV0005A-MFG]

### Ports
Isense_N_LV (out), Isense_P_LV (out), Switch_0_LV (in), Switch_1_LV (in), Switch_2_LV (in), Switch_3_LV (in), Switch_4_LV (in), Switch_5_LV (in), Switch_6_LV (in), Switch_7_LV (in), Switch_8_LV (in), Vsense_N_LV (out), Vsense_P_LV (out)

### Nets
GNDA: C9.2 C10.2 C11.2 C12.2 C13.2 C14.1 C15.1 C16.1 C17.1 C18.1 C140.2 C141.2 C142.1 C143.1 J1.2 J2.2 R32.1 TP3.1
GNDB: D1.1(K1) D2.1(K1) D3.1(K1) D4.2(K2) R24.1 R27.2 R29.I2  [also labelled Out_593]
VCC_LV_ext: C11.1 C12.1 C13.1 R211.2 U5.7(V+) U6.7(V+) U7.5(V+)
VDD_3V3: R22.1 R23.1 R30.1 R33.1 R34.1 R35.1 R36.1 R37.1 R38.1
VEE_LV_ext: C16.2 C17.2 C18.2 R213.2 U5.1(E/D_Com) U5.4(V-) U5.9(DAP) U6.1(E/D_Com) U6.4(V-) U6.9(DAP) U7.2(V-)
NetC9_1: C9.1 C10.1 J2.1 R210.1
NetC14_2: C14.2 C15.2 J2.3 R212.1
NetC140_1: C140.1 C141.1 R210.2 R211.1
NetC142_2: C142.2 C143.2 R212.2 R213.1
NetD1_2: D1.2(K2) R39.2 U5.2(IN-) ; port Isense_N_LV
NetD2_2: D2.2(K2) R41.1 ; port Isense_P_LV
NetD3_2: D3.2(K2) R43.2 R44.1 RN1.1 U6.2(IN-) ; port Vsense_P_LV
NetD4_1: D4.1(K1) R42.2 R43.1 RN1.2 ; port Vsense_N_LV
NetJ1_1: J1.1 K2.4(C) TP2.1
NetJ3_1: J3.1 R32.2 R46.2 R47.2
NetJ3_2: J3.2 R31.2 R45.2
NetK1_1: K1.1(Anode) R22.2
NetK1_2: K1.2(Cathode) ; port Switch_2_LV
NetK1_3: K1.3(1_Drain) K2.3(E) K3.4(C) K8.4(2_Drain) R26.2 R31.1 TP1.1
NetK1_4: K1.4(2_Drain) K7.4(2_Drain) K9.4(2_Drain) R25.2 R26.1
NetK2_1: K2.1(A) R23.2
NetK2_2: K2.2(K) ; port Switch_0_LV
NetK3_1: K3.1(A) R30.2
NetK3_2: K3.2(K) ; port Switch_1_LV
NetK3_3: K3.3(E) R24.2 R25.1 R28.2 R29.I1
NetK4_1: K4.1(Anode) R33.2
NetK4_2: K4.2(Cathode) ; port Switch_3_LV
NetK4_3: K4.3(1_Drain) K5.3(1_Drain) K7.3(1_Drain) R41.2
NetK4_4: K4.4(2_Drain) R27.1 R29.E2
NetK5_1: K5.1(Anode) R34.2
NetK5_2: K5.2(Cathode) ; port Switch_4_LV
NetK5_4: K5.4(2_Drain) K6.4(2_Drain) R28.1 R29.E1
NetK6_1: K6.1(Anode) R35.2
NetK6_2: K6.2(Cathode) ; port Switch_5_LV
NetK6_3: K6.3(1_Drain) K8.3(1_Drain) K9.3(1_Drain) R40.1
NetK7_1: K7.1(Anode) R36.2
NetK7_2: K7.2(Cathode) ; port Switch_6_LV
NetK8_1: K8.1(Anode) R38.2
NetK8_2: K8.2(Cathode) ; port Switch_8_LV
NetK9_1: K9.1(Anode) R37.2
NetK9_2: K9.2(Cathode) ; port Switch_7_LV
NetR39_1: R39.1 U5.6(OUT)
NetR40_2: R40.2 U5.3(IN+)
NetR42_1: R42.1 R47.1 RN1.3 U7.1(OUT) U7.4(-IN)
NetR44_2: R44.2 U6.6(OUT)
NetR45_1: R45.1 U6.3(IN+)
NetR46_1: R46.1 U7.3(+IN)

Not connected (* = marked no-connect by the designer): D1 3(A); D2 3(A); D3 3(A); D4 3(A); U5 5(Status_Flag) 8(E/D); U6 5(Status_Flag) 8(E/D)

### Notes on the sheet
- (near R24) Sensing 1V
  500mA@2 ohm 0.5W
  10mA@100 ohm 0.01W
  10uA@100k ohm
- (near J1) Reserve for local measure
- (near J2) Input +V=42V or 82V
- Input -V=-42V or -2V

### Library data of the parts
C9 C13 C14 C18 C140 C142 = CMP-0078499-1: CAP, CERM, 4.7 µF, 100 V,+/- 20%, X7S, 1206; Manufacturer: AVX; TaMin_C: -55°C; Polarized: N; SizeAreaWB_mm2: 10.92; U/M: EA; Value: 4.7uF; TaMax_C: 125°C; SizeZ_mm: 1.9; SizeX_mm: 3.2; SizeY_mm: 1.6; Cap_Case: 1206; SizeArea_mm2: 5.12; AEC Category: Q200
C10 C11 C15 C16 C141 C143 = CMP-0006618-2: CAP, CERM, 0.1 uF, 100 V, +/- 10%, X5R, 0402; Manufacturer: MuRata; SizeAreaWB_mm2: 3; SizeArea_mm2: 0.5; AEC Qualified: N; AEC Category: Q200; Value: 0.1uF; TaMax_C: 85°C; SizeZ_mm: 0.6; TaMin_C: -55°C; U/M: EA; SizeX_mm: 1; Value1: Unknown
C12 C17 = CMP-0006704-2: CAP, CERM, 2200 pF, 100 V, +/- 10%, X7R, 0402; Manufacturer: MuRata; TaMin_C: -55°C; Polarized: N; SizeAreaWB_mm2: 3; Value1: Unknown; U/M: EA; Value: 2200pF; TaMax_C: 125°C; SizeZ_mm: 0.6; SizeX_mm: 1; SizeY_mm: 0.5; Cap_F: 2.2nF; AEC Category: Q200
D1-D4 = CMP-0006013-3: Diode, Zener, 9.1 V, 0.18 W, AEC-Q101, SOT-323; Manufacturer: NXP Semiconductor; RJA_CperW: 680; SizeZ_mm: 1.1; Power_W: 180mW; SizeArea_mm2: 4.84; Vz_V: 9.1V; SizeX_mm: 2.2; SizeAreaWB_mm2: 10.24; Value1: 0.18W; AEC Qualified: Y; Value: 9.1V; AEC Category: Q101
J1 = CMP-0079044-1: Terminal Block, 5.08mm, 2x1, R/A, TH; Manufacturer: Wurth Elektronik; Pitch_mm: 5.08; Cert_VDE: Y; Gender: Female; Voltage_V: 300V; Current_A: 20A; Row_Count: 1
J2 = CMP-0079043-1: Terminal Block, 5.08mm, 3x1, R/A, TH; Manufacturer: Wurth Elektronik; Pitch_mm: 5.08; Cert_VDE: Y; Gender: Female; Voltage_V: 300V; Current_A: 20A; Row_Count: 1
J3 = CMP-0075483-1: Header, 100mil, 2x1, Gold, TH; Manufacturer: Samtec; Green_REACh: Passed; CT: False; Green_Lifecycle: Active; CNHeader: True
K1 K4-K9 = CMP-0095654-1: Manufacturer: Toshiba; On State Resistance: 8Ω; TJmax_C: +125°C; Input Current: 7.5mA; SizeZ_mm: 1.4mm; Contact Form: SPST-NO; AEC Qualified: No; Voltage_Isolation_Vrms: 500Vrms
K2 K3 = CMP-0080719-2: Relay, SPST-NO (1 Form A), 0.65 A, SMD; Manufacturer: Toshiba; SizeAreaWB_mm2: 7.35; SizeX_mm: 2; SizeZ_mm: 1.75; Contact Rating_A: 650mA; SizeY_mm: 1.45; SizeArea_mm2: 2.9
R22 R23 R30 R33-R38 = CMP-0026071-2: RES, 1.00 k, 1%, 0.063 W, 0402; Manufacturer: Vishay-Dale; Power_W: 63mW; TempCo: 100 ppm/C; Value_Code: 1k00; U/M: EA; Value: 1.00k; EIA_Code: E96; Res_ohm: 1k; SizeX_mm: 1; SizeY_mm: 0.5; SizeZ_mm: 0.6; Value2: 0.063W; VDC_V: 50V; AEC Category: Q200
R24 = CMP-0015029-2: RES, 2.00, 1%, 0.5 W, AEC-Q200 Grade 0, 1210; Manufacturer: Panasonic; Power_W: 500mW; TempCo: 100 ppm/C; Value_Code: 2R00; U/M: EA; Value: 2.00; EIA_Code: E96; Res_ohm: 2; SizeX_mm: 3.2; SizeY_mm: 2.5; SizeZ_mm: 1.35; Value2: 0.5W; SizeArea_mm2: 8; AEC Qualified: Y; AEC Category: Q200; AEC Grade: 0; SizeAreaWB_mm2: 14.7
R25 = CMP-0020835-3: RES, 100, 1%, 0.125 W, AEC-Q200 Grade 0, 0805; Manufacturer: Vishay-Dale; Power_W: 125mW; TempCo: 100 ppm/C; Value_Code: 100R; Value: 100; EIA_Code: E96; SizeX_mm: 2; SizeY_mm: 1.25; SizeZ_mm: 1.45; Value2: 0.125W; SizeArea_mm2: 2.5; AEC Qualified: Y; VDC_V: 150V; AEC Category: Q200; AEC Grade: 0
R26 = CMP-0020834-2: RES, 100 k, 1%, 0.125 W, 0805; Manufacturer: Vishay-Dale; Power_W: 125mW; TempCo: 100 ppm/C; U/M: EA; Value: 100k; EIA_Code: E96; SizeX_mm: 2; SizeY_mm: 1.25; SizeZ_mm: 1.45; Value2: 0.125W; SizeArea_mm2: 2.5; VDC_V: 150V; AEC Category: Q200
R27 R28 R31 R32 R47 = CMP-0026822-3: as R134 on sheet FVI80_Signal_ADC93
R29 = CMP-0126086-1: 2 Ohms ±1% 0.5W, 1/2W Chip Resistor Wide 2516 (6440 Metric), 1625 Current Sense, Moisture Resistant, Non-Inductive Metal Foil; Manufacturer: VPG Foil Resistors; AEC Qualified: No; Power_W: 500mW; Res_ohm: 2; SizeZ_mm: 1.02mm; TempCo: 2ppm/°C; Value: 2
R39 R44 = CMP-0021039-1: RES, 200, 1%, 0.125 W, 0805; Manufacturer: Vishay-Dale; Power_W: 125mW; TempCo: 100 ppm/C; Value_Code: 200R; U/M: EA; Value: 200; EIA_Code: E96; SizeX_mm: 2; SizeY_mm: 1.25; SizeZ_mm: 1.45; Value2: 0.125W; SizeArea_mm2: 2.5; VDC_V: 150V; AEC Category: Q200
R40 R41 R45 R46 = CMP-0026763-1: as R138 on sheet FVI80_Signal_ADC93
R42 = CMP-0021721-3: RES, 45.3 k, 1%, 0.125 W, AEC-Q200 Grade 0, 0805; Manufacturer: Panasonic; Power_W: 125mW; TempCo: 100 ppm/C; Value_Code: 45k3; Value: 45.3k; EIA_Code: E96; SizeX_mm: 2; SizeY_mm: 1.25; SizeZ_mm: 1.45; Value2: 0.125W; SizeArea_mm2: 2.5; AEC Qualified: Y; AEC Category: Q200; AEC Grade: 0; SizeAreaWB_mm2: 6.75
R43 = CMP-0088945-1: 5 kOhms ±1% 0.125W, 1/8W Chip Resistor 0805 (2012 Metric) Automotive AEC-Q200 Thick Film; Manufacturer: Vishay Dale; VDC_V: 150V; AEC Grade: Grade 0; Power_W: 125mW; SizeZ_mm: 0.5mm; AEC Qualified: Yes; TempCo: 100ppm/°C
R210-R213 = CMP-0023338-2: RES, 0.2, 1%, 0.2 W, AEC-Q200 Grade 0, 0603; Manufacturer: Vishay-Dale; Power_W: 200mW; TempCo: 100 ppm/C; Value_Code: R200; U/M: EA; Value: 0.2; EIA_Code: E96; SizeX_mm: 1.6; SizeY_mm: 0.8; SizeZ_mm: 1; Value2: 0.2W; SizeArea_mm2: 1.28; AEC Qualified: Y; AEC Grade: 0; AEC Category: Q200
RN1 = CMP-0126296-1: 2k, 18k Ohm ±0.005% 500mW Power Per Element Voltage Divider 2 Resistor Network/Array ±0.2ppm/°C Radial - 3 Leads; Manufacturer: VPG Foil Resistors; AEC Qualified: No; Power_W: 1W; Value: 2/18kΩ; VDC_V: 350V; Number Of Resistors: 2; Power Per Resistor: 0.5W; SizeZ_mm: 10.7mm; Standoff Height: 0.3mm
TP1 TP2 = CMP-0055137-2: Test Point, Miniature, Red, TH; Manufacturer: Keystone Electronics; Green_REACh: Passed; Green_Lifecycle: Active; ContactFinish: Silver; CNHeader: FALSE; CT: TRUE
TP3 = CMP-0055138-1: Test Point, Miniature, Black, TH; Manufacturer: Keystone; CNHeader: FALSE; Green_Lifecycle: Active; Green_REACh: Passed; ContactFinish: Silver; CT: TRUE
U5 U6 = CMP-0043744-3: High Voltage (100V), High-Current (50mA) Operational Amplifiers, G=1 Stable, DDA0008J (HSOIC-8); Manufacturer: Texas Instruments; SizeAreaWB_mm2: 55.2; SizeX_mm: 6; Iq per channel(Max)(mA): 4; Total Supply Voltage(Max)(+5V is 5, +/-5V is 10): 100; Offset Drift(Typ)(uV/C): 1.6; Vn at 1kHz(Typ)(nV/rtHz): 47; Slew Rate(Typ)(V/us): 13; Number of Channels: 1; Total Supply Voltage(Min)(+5V is 5, +/-5V is 10): 10; CompType: IC; Rating: Catalog; AEC Category: Q200; GBW(Typ)(MHz): 2.5; SizeArea_mm2: 29.4; SizeY_mm: 4.9; AEC Qualified: N; SizeZ_mm: 1.7
U7 = CMP-0126324-1: 85V high speed (100V/µs) to power (400µA) ratio precision op-amp in small package 5-SOT-23 -40 to 125; Manufacturer: Texas Instruments; SizeZ_mm: 1.45mm; AEC Qualified: No; Gain Bandwidth: 3.75MHz; Input Bias Current: 5pA; Input Offset Voltage: 0.2mV; Max Dual Supply Voltage: 42.5V; Min Dual Supply Voltage: 4V; Min Supply Voltage: 8V; Nominal Supply Current: 420uA; Number Of Channels: 1; Output Current Per Channel: 30mA; Response Time: 3us; Standoff Height: 0mm; TaMax_C: +125°C; TaMin_C: -40°C; TJmax_C: +150°C; Voltage Gain: 140dB

## Sheet FVI80_FPGA_Connector.SchDoc
size 431 x 279 mm; Date: Not shown in title block; ApprovedBy: Not shown in title block; CheckedBy: Not shown in title block; Author: Not shown in title block; CompanyName: Not shown in title block; Engineer: Not shown in title block; Organization: Not shown in title block; Address1: Not shown in title block; Address2: Not shown in title block; Address3: Not shown in title block; Address4: Not shown in title block; DocumentNumber: 10; Revision: Use project parameter SCH_Rev; SheetNumber: 10; SheetTotal: 11; PageSetup: Record=PageOptions¦CenterHorizontal=True¦CenterVertical=True¦PrintScale=1.00¦XCorrection=1.00¦YCorrection=1.00¦PrintKind=0¦BorderSize=5000000¦LeftOffset=0¦BottomOffset=0¦Orientation=2¦PaperLength=1000¦PaperWidth=1000¦Scale=100¦PaperSource=15¦PrintQuality=600¦MediaType=1¦DitherType=10¦PaperKind=Letter¦PrintScaleMode=1
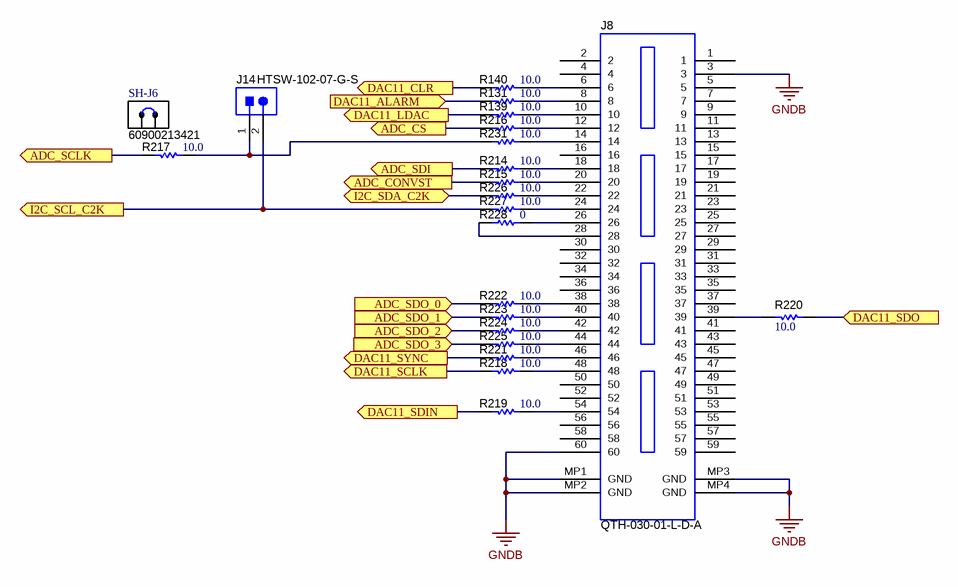
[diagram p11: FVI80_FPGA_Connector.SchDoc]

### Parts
J8  QTH-030-01-L-D-A  [Samtec_QTH-030-01-x-D-A]
J14  HTSW-102-07-G-S  [Samtec_HTSW-102-07-G-S]
R131  ValueDisplayed: 10.0  [0402]  (hidden comment: MCR01MZPF10R0)
R139  ValueDisplayed: 10.0  [0402]  (hidden comment: MCR01MZPF10R0)
R140  ValueDisplayed: 10.0  [0402]  (hidden comment: MCR01MZPF10R0)
R214  ValueDisplayed: 10.0  [0402]  (hidden comment: MCR01MZPF10R0)
R215  ValueDisplayed: 10.0  [0402]  (hidden comment: MCR01MZPF10R0)
R216  ValueDisplayed: 10.0  [0402]  (hidden comment: MCR01MZPF10R0)
R217  ValueDisplayed: 10.0  [0402]  (hidden comment: MCR01MZPF10R0)
R218  ValueDisplayed: 10.0  [0402]  (hidden comment: MCR01MZPF10R0)
R219  ValueDisplayed: 10.0  [0402]  (hidden comment: MCR01MZPF10R0)
R220  ValueDisplayed: 10.0  [0402]  (hidden comment: MCR01MZPF10R0)
R221  ValueDisplayed: 10.0  [0402]  (hidden comment: MCR01MZPF10R0)
R222  ValueDisplayed: 10.0  [0402]  (hidden comment: MCR01MZPF10R0)
R223  ValueDisplayed: 10.0  [0402]  (hidden comment: MCR01MZPF10R0)
R224  ValueDisplayed: 10.0  [0402]  (hidden comment: MCR01MZPF10R0)
R225  ValueDisplayed: 10.0  [0402]  (hidden comment: MCR01MZPF10R0)
R226  ValueDisplayed: 10.0  [0402]  (hidden comment: MCR01MZPF10R0)
R227  ValueDisplayed: 10.0  [0402]  (hidden comment: MCR01MZPF10R0)
R228  ValueDisplayed: 0  [0402]  (hidden comment: CRCW04020000Z0ED)
R231  ValueDisplayed: 10.0  [0402]  (hidden comment: MCR01MZPF10R0)
SH-J6  60900213421  [Wurth_60900213421]

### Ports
ADC_CONVST (out), ADC_CS (out), ADC_SCLK (out), ADC_SDI (out), ADC_SDO_0 (in), ADC_SDO_1 (in), ADC_SDO_2 (in), ADC_SDO_3 (in), DAC11_ALARM (in), DAC11_CLR (out), DAC11_LDAC (out), DAC11_SCLK (out), DAC11_SDIN (out), DAC11_SDO (in), DAC11_SYNC (out), I2C_SCL_C2K (out), I2C_SDA_C2K (bidir)

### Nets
GNDB: J8.3 J8.60 J8.MP1(GND) J8.MP2(GND) J8.MP3(GND) J8.MP4(GND)
I2C_SCL_IN: J14.2 R227.1 ; port I2C_SCL_C2K
I2C_SDA_IN: R226.1 ; port I2C_SDA_C2K
NetJ8_6: J8.6 R140.2
NetJ8_8: J8.8 R131.2
NetJ8_10: J8.10 R139.2
NetJ8_12: J8.12 R216.2
NetJ8_14: J8.14 R231.2
NetJ8_18: J8.18 R214.2
NetJ8_20: J8.20 R215.2
NetJ8_22: J8.22 R226.2
NetJ8_24: J8.24 R227.2
NetJ8_26: J8.26 R228.2
NetJ8_28: J8.28 R228.1
NetJ8_38: J8.38 R222.2
NetJ8_39: J8.39 R220.1
NetJ8_40: J8.40 R223.2
NetJ8_42: J8.42 R224.2
NetJ8_44: J8.44 R225.2
NetJ8_46: J8.46 R221.1
NetJ8_48: J8.48 R218.1
NetJ8_54: J8.54 R219.1
NetJ14_1: J14.1 R217.2 R231.1
NetR115_1: R131.1 ; port DAC11_ALARM
NetR116_1: R140.1 ; port DAC11_CLR
NetR117_1: R139.1 ; port DAC11_LDAC
NetR118_1: R221.2 ; port DAC11_SYNC
NetR134_1: R215.1 ; port ADC_CONVST
NetR134_2: R216.1 ; port ADC_CS
NetR170_2: R222.1 ; port ADC_SDO_0
NetR172_2: R223.1 ; port ADC_SDO_1
NetR174_2: R224.1 ; port ADC_SDO_2
NetR178_1: R214.1 ; port ADC_SDI
NetR179_1: R225.1 ; port ADC_SDO_3
NetR181_1: R217.1 ; port ADC_SCLK
NetR185_1: R219.2 ; port DAC11_SDIN
NetR186_1: R220.2 ; port DAC11_SDO
NetR187_1: R218.2 ; port DAC11_SCLK

Not connected (* = marked no-connect by the designer): J8 1 2 4 5 7 9 11 13 15 16 17 19 21 23 25 27 29 30 31 32 33 34 35 36 37 41 43 45 47 49 50 51 52 53 55 56 57 58 59

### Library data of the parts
J8 = CMP-0075558-1: Header(Shrouded), 19.7mil, 30x2, Gold, SMT; Manufacturer: Samtec; Pitch_mm: 0.5; Gender: Male; Green_REACh: Passed; CT: False; Shrouded: Y; Green_Lifecycle: Active; Row_Count: 2
J14 = CMP-0075483-1: as J3 on sheet FVI80_Power_Rsense_series
R131 R139 R140 R214-R227 R231 = CMP-0025963-3: as R189-R192 on sheet FVI80_HV_Power_Connector
R228 = CMP-0026822-3: as R134 on sheet FVI80_Signal_ADC93
SH-J6 = CMP-0003761-2: Shunt, 2.54mm, Gold, Black; Manufacturer: Wurth Elektronik

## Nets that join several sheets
GNDA: FVI80_Power_OPA593 (26 pins), FVI80_Power_Rsense_series (18 pins)
GNDB: FVI80_Power_OPA593 (5 pins), FVI80_Signal_biasPower (84 pins), FVI80_Signal_DAC (56 pins), FVI80_Signal_CCCV (53 pins), FVI80_C2000_Connector (22 pins), FVI80_MUX_Signal (15 pins), FVI80_HV_Power_Connector (31 pins), FVI80_Signal_ADC93 (35 pins), FVI80_Power_Rsense_series (7 pins), FVI80_FPGA_Connector (6 pins)
REF_2.5: FVI80_Signal_DAC (C54.1 C55.2 R121.2), FVI80_Signal_ADC93 (U37.11 U37.17)
REF_4: FVI80_Signal_DAC (C65.1 C72.2 R233.2), FVI80_Signal_CCCV (R94.1)
REF_4096: FVI80_Signal_DAC (7 pins), FVI80_Signal_CCCV (R68.2), FVI80_Signal_ADC93 (R138.2)
REF_4096N: FVI80_Signal_DAC (5 pins), FVI80_Signal_CCCV (R75.2 R99.1)
VCC_LV_ext: FVI80_Power_OPA593 (8 pins), FVI80_Power_Rsense_series (7 pins)
VDD_3V3: FVI80_Signal_biasPower (7 pins), FVI80_Signal_DAC (8 pins), FVI80_Signal_CCCV (5 pins), FVI80_MUX_Signal (9 pins), FVI80_Signal_ADC93 (7 pins), FVI80_Power_Rsense_series (9 pins)
VDD_5V: FVI80_Signal_biasPower (8 pins), FVI80_Signal_DAC (12 pins), FVI80_HV_Power_Connector (7 pins), FVI80_Signal_ADC93 (13 pins)
VDD_5V_C2K: FVI80_Signal_biasPower (C116.1 C117.1 FB2.2), FVI80_C2000_Connector (8 pins)
VDD_12VN: FVI80_Signal_biasPower (C123.2 C124.2 J13.2), FVI80_Signal_DAC (12 pins), FVI80_Signal_CCCV (24 pins), FVI80_MUX_Signal (C45.1 U24.3 U25.3), FVI80_HV_Power_Connector (7 pins)
VDD_12VP: FVI80_Signal_biasPower (7 pins), FVI80_Signal_DAC (9 pins), FVI80_Signal_CCCV (24 pins), FVI80_MUX_Signal (C42.2 U24.13 U25.11), FVI80_HV_Power_Connector (7 pins)
VEE_LV_ext: FVI80_Power_OPA593 (20 pins), FVI80_Power_Rsense_series (11 pins)
I2C_SCL_IN: FVI80_Signal_DAC (U31.6), FVI80_C2000_Connector (R175.1), FVI80_MUX_Signal (U23.19 U26.19), FVI80_HV_Power_Connector (R189.1), FVI80_FPGA_Connector (J14.2 R227.1)
I2C_SDA_IN: FVI80_Signal_DAC (U31.8), FVI80_C2000_Connector (R173.1), FVI80_MUX_Signal (U23.20 U26.20), FVI80_HV_Power_Connector (R190.1), FVI80_FPGA_Connector (R226.1)
NetC19_1: FVI80_Signal_CCCV (C19.1 R51.1 R60.2 U9.11), FVI80_Signal_ADC93 (RN7.3)
NetC36_1: FVI80_Signal_CCCV (C36.1 R89.1 U15.11), FVI80_Signal_ADC93 (RN6.3)
NetC39_2: FVI80_Signal_CCCV (6 pins), FVI80_MUX_Signal (U25.2 U25.8)
NetC56_1: FVI80_Signal_DAC (C56.1 R123.2 U30.1), FVI80_Signal_CCCV (U17.2)
NetD1_2: FVI80_MUX_Signal (U24.5), FVI80_HV_Power_Connector (R196.1), FVI80_Power_Rsense_series (D1.2 R39.2 U5.2)
NetD2_2: FVI80_MUX_Signal (U24.2), FVI80_HV_Power_Connector (R195.1), FVI80_Power_Rsense_series (D2.2 R41.1)
NetD3_2: FVI80_MUX_Signal (U24.12), FVI80_HV_Power_Connector (R193.1), FVI80_Power_Rsense_series (5 pins)
NetD4_1: FVI80_MUX_Signal (U24.14), FVI80_HV_Power_Connector (R194.1), FVI80_Power_Rsense_series (D4.1 R42.2 R43.1 RN1.2)
NetK1_2: FVI80_MUX_Signal (U23.3), FVI80_Power_Rsense_series (K1.2)
NetK2_2: FVI80_MUX_Signal (U23.1), FVI80_Power_Rsense_series (K2.2)
NetK3_2: FVI80_MUX_Signal (U23.2), FVI80_Power_Rsense_series (K3.2)
NetK4_2: FVI80_MUX_Signal (U23.4), FVI80_Power_Rsense_series (K4.2)
NetK5_2: FVI80_MUX_Signal (U23.5), FVI80_Power_Rsense_series (K5.2)
NetK6_2: FVI80_MUX_Signal (U23.6), FVI80_Power_Rsense_series (K6.2)
NetK7_2: FVI80_MUX_Signal (U23.7), FVI80_Power_Rsense_series (K7.2)
NetK8_2: FVI80_MUX_Signal (U23.10), FVI80_Power_Rsense_series (K8.2)
NetK9_2: FVI80_MUX_Signal (U23.8), FVI80_Power_Rsense_series (K9.2)
NetR3_1: FVI80_Power_OPA593 (R3.1), FVI80_MUX_Signal (U25.1)
NetR52_1: FVI80_Signal_CCCV (R52.1 R56.1), FVI80_MUX_Signal (U24.6)
NetR58_1: FVI80_Signal_CCCV (R58.1 R59.1), FVI80_MUX_Signal (U24.1)
NetR62_1: FVI80_Signal_DAC (R129.2 U33.3 U33.7), FVI80_Signal_CCCV (R62.1 RN2.1)
NetR91_1: FVI80_Signal_CCCV (R91.1 R92.1), FVI80_MUX_Signal (U24.15)
NetR93_1: FVI80_Signal_CCCV (R93.1 R95.1), FVI80_MUX_Signal (U24.11)
NetR114_1: FVI80_MUX_Signal (R114.1), FVI80_HV_Power_Connector (R198.1)
NetR115_1: FVI80_Signal_DAC (R115.1 U27.19), FVI80_C2000_Connector (R182.1), FVI80_FPGA_Connector (R131.1)
NetR116_1: FVI80_Signal_DAC (R116.1 U27.30), FVI80_C2000_Connector (R184.1), FVI80_FPGA_Connector (R140.1)
NetR117_1: FVI80_Signal_DAC (R117.1 U27.18), FVI80_C2000_Connector (R180.1), FVI80_FPGA_Connector (R139.1)
NetR118_1: FVI80_Signal_DAC (R118.1 U27.33), FVI80_C2000_Connector (R188.1), FVI80_FPGA_Connector (R221.2)
NetR128_2: FVI80_Signal_DAC (R128.2 U32.3 U32.7), FVI80_Signal_CCCV (RN3.7)
NetR134_1: FVI80_C2000_Connector (R177.1), FVI80_Signal_ADC93 (R134.1 U36.10), FVI80_FPGA_Connector (R215.1)
NetR134_2: FVI80_C2000_Connector (R183.1), FVI80_Signal_ADC93 (R134.2 R135.1 U36.11), FVI80_FPGA_Connector (R216.1)
NetR163_2: FVI80_C2000_Connector (R163.2), FVI80_Signal_ADC93 (U38.3 U38.4)
NetR165_2: FVI80_Signal_CCCV (U12.2), FVI80_C2000_Connector (R165.2)
NetR166_2: FVI80_Signal_CCCV (U12.8), FVI80_C2000_Connector (R166.2)
NetR167_2: FVI80_C2000_Connector (R167.2), FVI80_Signal_ADC93 (U35.3 U35.4)
NetR169_1: FVI80_C2000_Connector (R169.1), FVI80_HV_Power_Connector (R192.1)
NetR170_2: FVI80_C2000_Connector (R170.2), FVI80_Signal_ADC93 (U36.16), FVI80_FPGA_Connector (R222.1)
NetR171_1: FVI80_C2000_Connector (R171.1), FVI80_HV_Power_Connector (R191.1)
NetR172_2: FVI80_C2000_Connector (R172.2), FVI80_Signal_ADC93 (U36.15), FVI80_FPGA_Connector (R223.1)
NetR174_2: FVI80_C2000_Connector (R174.2), FVI80_Signal_ADC93 (U36.14), FVI80_FPGA_Connector (R224.1)
NetR178_1: FVI80_C2000_Connector (R178.1), FVI80_Signal_ADC93 (U36.12), FVI80_FPGA_Connector (R214.1)
NetR179_1: FVI80_C2000_Connector (R179.1), FVI80_Signal_ADC93 (U36.13), FVI80_FPGA_Connector (R225.1)
NetR181_1: FVI80_C2000_Connector (R181.1), FVI80_Signal_ADC93 (U36.17), FVI80_FPGA_Connector (R217.1)
NetR185_1: FVI80_Signal_DAC (U27.32), FVI80_C2000_Connector (R185.1), FVI80_FPGA_Connector (R219.2)
NetR186_1: FVI80_Signal_DAC (U27.34), FVI80_C2000_Connector (R186.1), FVI80_FPGA_Connector (R220.2)
NetR187_1: FVI80_Signal_DAC (U27.31), FVI80_C2000_Connector (R187.1), FVI80_FPGA_Connector (R218.2)
NetR197_2: FVI80_MUX_Signal (U26.13), FVI80_HV_Power_Connector (R197.2)
NetR199_2: FVI80_MUX_Signal (U26.14), FVI80_HV_Power_Connector (R199.2)
NetR200_1: FVI80_MUX_Signal (U24.20), FVI80_HV_Power_Connector (R200.1 R204.1)
NetR201_2: FVI80_MUX_Signal (U26.15), FVI80_HV_Power_Connector (R201.2)
NetR202_1: FVI80_MUX_Signal (U24.7), FVI80_HV_Power_Connector (R202.1 R204.2)
NetR203_2: FVI80_MUX_Signal (U26.16), FVI80_HV_Power_Connector (R203.2)
NetR205_1: FVI80_MUX_Signal (U24.10), FVI80_HV_Power_Connector (R205.1 R208.1)
NetR206_2: FVI80_MUX_Signal (U26.17), FVI80_HV_Power_Connector (R206.2)
NetR207_1: FVI80_MUX_Signal (U24.16), FVI80_HV_Power_Connector (R207.1 R208.2)
NetR209_1: FVI80_MUX_Signal (U25.9), FVI80_HV_Power_Connector (R209.1)
NetU11_6: FVI80_Signal_CCCV (U11.6 U11.7 U39.6 U39.7), FVI80_MUX_Signal (U23.15)
NetU16_6: FVI80_Signal_CCCV (U16.6), FVI80_MUX_Signal (U23.13)
NetU17_6: FVI80_Signal_CCCV (U17.6), FVI80_MUX_Signal (U23.11)
NetU18_6: FVI80_Signal_CCCV (U18.6 U18.15), FVI80_MUX_Signal (U23.16)
NetU18_12: FVI80_Signal_CCCV (U18.12), FVI80_MUX_Signal (U23.17)
NetU20_5: FVI80_Signal_CCCV (U20.5), FVI80_MUX_Signal (U23.14)
NetU20_6: FVI80_Signal_CCCV (U20.6), FVI80_MUX_Signal (U23.12)
NetU21_6: FVI80_Signal_CCCV (U21.6), FVI80_MUX_Signal (U26.4)
NetU21_7: FVI80_Signal_CCCV (U21.7), FVI80_MUX_Signal (U26.3)
NetU21_14: FVI80_Signal_CCCV (U21.14), FVI80_MUX_Signal (U26.2)
NetU21_15: FVI80_Signal_CCCV (U21.15), FVI80_MUX_Signal (U26.1)
NetU22_6: FVI80_Signal_CCCV (U22.6), FVI80_MUX_Signal (U26.8)
NetU22_7: FVI80_Signal_CCCV (U22.7), FVI80_MUX_Signal (U26.7)
NetU22_14: FVI80_Signal_CCCV (U22.14), FVI80_MUX_Signal (U26.6)
NetU22_15: FVI80_Signal_CCCV (U22.15), FVI80_MUX_Signal (U26.5)

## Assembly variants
001: not fitted C20 C27 C35 C38 C53 C56 J3 J6 J7 J9 J12 J18 R29 R47 R50 R56 R57 R58 R66 R81 R90 R92 R93 R99 R100 R105 R126 R128 R129 R134 R141 R231 RN1 RN2 SH-J1 SH-J4 SH-J6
